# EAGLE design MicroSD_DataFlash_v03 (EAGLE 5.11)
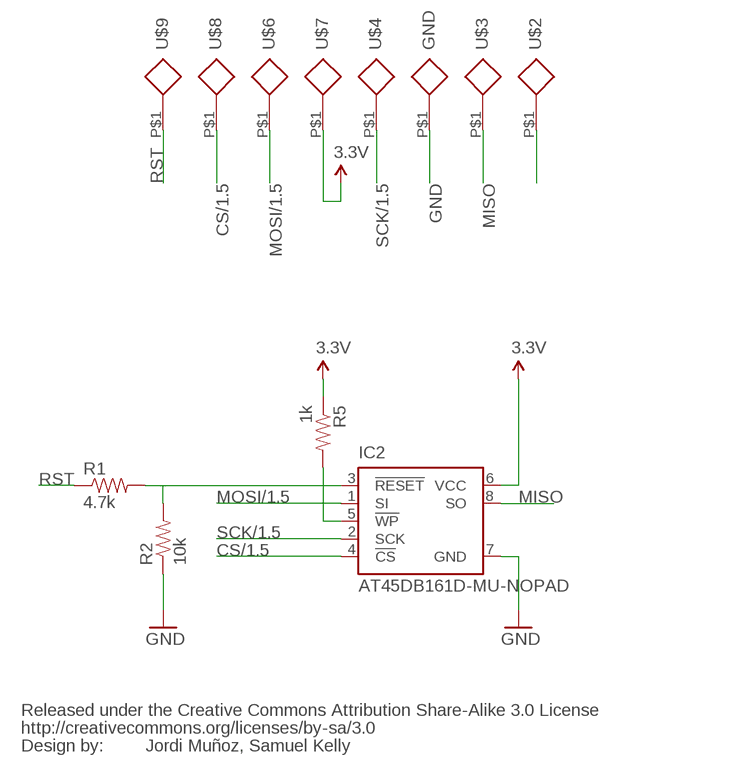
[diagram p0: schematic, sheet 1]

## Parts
GND  MICROSD-PAD3.2MM  [MICROSD-PAD-3.2MM]
IC2  AT45DB161D-MU-NOPAD  [VDFN-8-NO-BOTTOM-PAD]
R1  4.7k  RESISTOR0402-RES  [0402-RES]
R2  10k  RESISTOR0402-RES  [0402-RES]
R5  1k  RESISTOR0402-RES  [0402-RES]
U$1  CREATIVE_COMMONS  [CREATIVE_COMMONS]
U$2  MICROSD-PAD2.9MM  [MICROSD-PAD-2.9MM]
U$3  MICROSD-PAD2.9MM  [MICROSD-PAD-2.9MM]
U$4  MICROSD-PAD2.9MM  [MICROSD-PAD-2.9MM]
U$6  MICROSD-PAD2.9MM  [MICROSD-PAD-2.9MM]
U$7  MICROSD-PAD3.2MM  [MICROSD-PAD-3.2MM]
U$8  MICROSD-PAD2.9MM  [MICROSD-PAD-2.9MM]
U$9  MICROSD-PAD2.9MM  [MICROSD-PAD-2.9MM]

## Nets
3.3V: IC2.6(VCC) R5.1 U$7.P$1
CS/1.5: IC2.4(!CS) U$8.P$1
GND: GND.P$1 IC2.7(GND) R2.1
MISO: IC2.8(SO) U$3.P$1
MOSI/1.5: IC2.1(SI) U$6.P$1
N$2: IC2.3(!RESET) R1.2 R2.2
N$3: IC2.5(!WP) R5.2
N$11: U$2.P$1
RST: R1.1 U$9.P$1
SCK/1.5: IC2.2(SCK) U$4.P$1

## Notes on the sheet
- Jordi Muñoz, Samuel Kelly

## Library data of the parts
GND U$2-U$4 U$6-U$9 = 3DRobotics:MICROSD-PAD
IC2 = 3DRobotics:AT45DB161D: Atmel 16-megabit 2.5V or 2.7V DataFlash The Atmel® AT45DB161D is a 2.5V or 2.7V, serial-interface sequential access Flash memory ideally suited for a wide variety of digital voice-, image-, program code- and data-storage applications. The AT45DB161D supports Atmel RapidS? serial interface for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; DATASHEET: http://www.atmel.com/dyn/resources/prod_documents/doc3500.pdf; LINK: http://www.atmel.com/dyn/products/product_card.asp?part_id=3772; MFGPN: AT45DB161D-MU
R1 R2 R5 = SparkFun:RESISTOR: Resistor
U$1 = SparkFun:CREATIVE_COMMONS

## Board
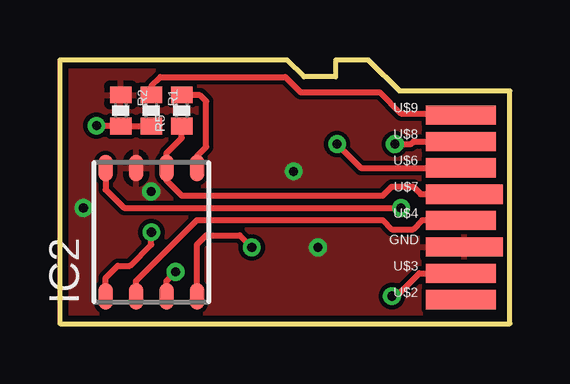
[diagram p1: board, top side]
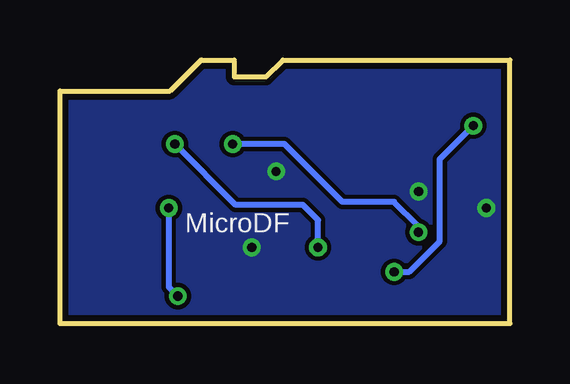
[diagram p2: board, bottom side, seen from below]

Size 18.76 x 11 mm. Coordinates in mm from the lower left corner, seen from the top.
Outline: 0,0 0,11 9.47,11 10.17,10.3 11.5,10.3 11.5,11 12.87,11 14.17,9.7 18.76,9.7 18.76,0 0,0
Copper layers (1*2+15*16): Top 0.035mm / dielectric 1.5mm / Route2 0.035mm / dielectric 0.15mm / Route15 0.035mm / dielectric 0.2mm / Bottom 0.035mm
Design rules "3DRobotics_4layers": minimum track width 7mil, minimum drill 15mil, track to track 7mil, track to pad 7mil, pad to pad 7mil, via to via 7mil, smd to smd 0mil, copper to edge 10mil, drill to drill 8mil, minimum pad ring 7mil, minimum via ring 7mil, stop-mask expansion 4mil, vias tented up to drill 25mil, thermal gap 10mil

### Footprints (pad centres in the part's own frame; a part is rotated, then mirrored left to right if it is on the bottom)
MICROSD-PAD-3.2MM = smd 0.8 x 3.2: P$1 0,0
VDFN-8-NO-BOTTOM-PAD = smd 1.1 x 0.6: 1 -2.675,1.905; 2 -2.675,0.635; 3 -2.675,-0.635; 4 -2.675,-1.905; 5 2.675,-1.905; 6 2.675,-0.635; 7 2.675,0.635; 8 2.675,1.905
0402-RES = smd 0.7 x 0.9: 1 -0.65,0; 2 0.65,0
MICROSD-PAD-2.9MM = smd 0.8 x 2.9: P$1 0,0

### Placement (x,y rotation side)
GND  16.87,3.2 90 top
IC2  3.81,3.81 90 top
R1  3.81,8.89 270 top
R2  2.54,8.89 270 top
R5  5.08,8.89 90 top
U$1  not placed on the board
U$2  16.72,1 90 top
U$3  16.72,2.1 90 top
U$4  16.72,4.3 90 top
U$6  16.72,6.5 90 top
U$7  16.87,5.4 90 top
U$8  16.72,7.6 90 top
U$9  16.72,8.7 90 top

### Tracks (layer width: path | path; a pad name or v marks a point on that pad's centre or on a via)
3.3V
  Top 0.254: R5.1 5.08,7.75 4.45,7.11 IC2.6 4.45,5.97 5.08,5.33 13.46,5.33 13.84,5.71 14.73,5.71 15.05,5.4 U$7.P$1
CS/1.5  (via drill 0.38)
  Top 0.254: U$8.P$1 14.75,7.6 14.64,7.49 v13.97,7.49 | IC2.4 5.71,3.3 6.1,3.68 7.49,3.68 v8,3.17
  Bottom 0.254: v8,3.17 8,4.32 8.64,4.95 11.43,4.95 v13.97,7.49
GND  (via drill 0.38)
  other vias: 9.74,6.35 0.98,4.83 10.76,3.17 3.8,5.51
  pour Top: 0,0 0,12.7 19.51,12.7 19.51,0
  pour Bottom: 0,0 0,13.97 19.51,13.97 19.51,0
MISO  (via drill 0.38)
  Top 0.254: v13.84,1.14 14.03,1.14 14.99,2.1 U$3.P$1 | IC2.8 1.91,5.59 2.67,4.83 v14.22,4.83
  Bottom 0.254: v14.22,4.83 14.22,1.52 v13.84,1.14
MOSI/1.5  (via drill 0.38)
  Top 0.254: U$6.P$1 12.55,6.5 v11.56,7.49 | IC2.1 1.91,1.91 2.41,2.41 2.92,2.41 3.81,3.3 v3.81,3.81
  Bottom 0.254: v11.56,7.49 9.4,7.49 6.99,5.08 4.83,5.08 3.81,4.06 v3.81,3.81
N$2  (via drill 0.38)
  Top 0.254: R1.2 R2.2 2.52,8.26 v1.52,8.26 | IC2.3 4.45,1.78 v4.83,2.16
  Bottom 0.254: v4.83,2.16 4.19,2.16 2.92,3.43 2.92,6.86 v1.52,8.26
N$3
  Top 0.254: IC2.5 5.71,6.99 6.1,7.37 6.1,9.27 5.84,9.53 5.09,9.53 R5.2
RST
  Top 0.254: R1.1 3.81,9.9 4.19,10.29 9.4,10.29 10.03,9.65 13.34,9.65 14.22,8.76 16.66,8.76 U$9.P$1
SCK/1.5
  Top 0.254: IC2.2 3.17,1.78 5.71,4.32 13.46,4.32 13.84,3.94 14.73,3.94 15.11,4.32 16.7,4.32 U$4.P$1

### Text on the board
bPlace: MicroDF
tDocu: Jordi Muñoz, Samuel Kelly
